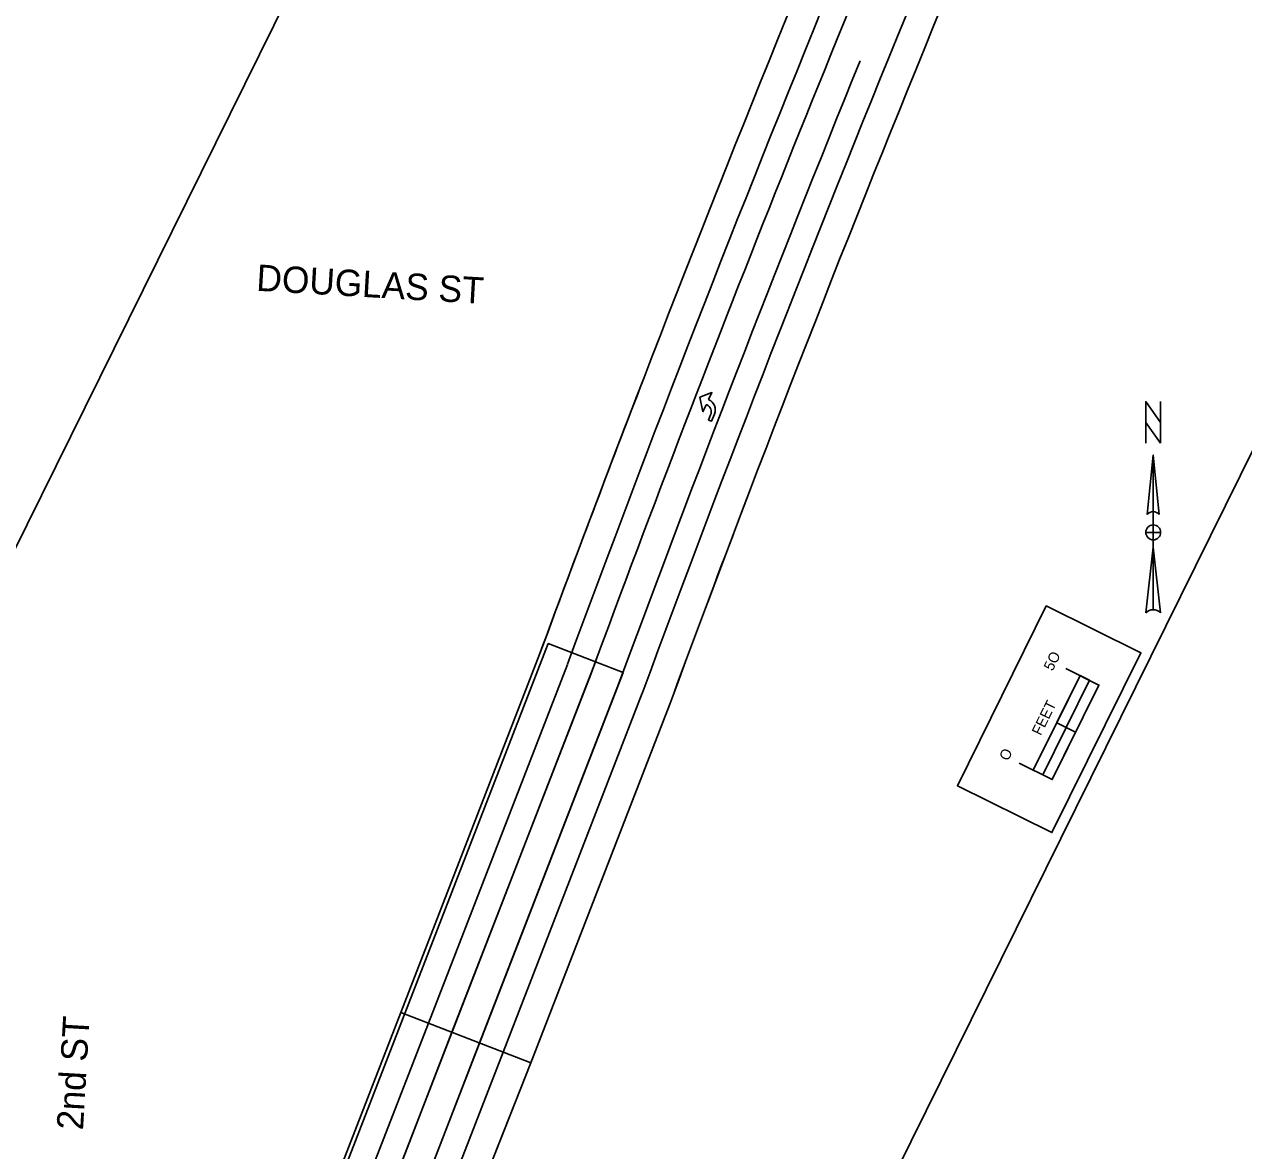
# Model space of a CAD drawing. Extents: x 14104283 to 14120882, y 8635219 to 8671666.
# Drawn here: x 14119794 to 14120371, y 8670437 to 8670971 of the extents above; entities that cross this region are included whole.
import ezdxf

# ---------------------------------------------------------------- set-up
doc = ezdxf.new("R2010")
doc.units = 0
for name, color, linetype in [('Cell', 7, 'Continuous'), ('Default', 7, 'Continuous'), ('dsnCellsNorthArrow', 7, 'Continuous'), ('dsnCellsScaleBlock', 7, 'Continuous'), ('dsnNonPlotable', 7, 'Continuous'), ('dsnPaintExistingBrokenLaneLineWhite', 7, 'Continuous'), ('dsnPaintExistingEdgeLineRightWhite', 7, 'Continuous'), ('dsnPaintExistingNoPassingYellow', 7, 'Continuous'), ('dsnPaintExistingSymbolWhite', 7, 'Continuous'), ('dsnShadingPaved', 7, 'Continuous'), ('dsnTextOverlapEven', 7, 'Continuous'), ('dsnTextOverlapOdd', 7, 'Continuous')]:
    doc.layers.add(name, color=color, linetype=linetype)

msp = doc.modelspace()

# ---------------------------------------------------------------- linework, layer by layer
at = {"layer": 'Cell'}
for p, q in [((14120117.15, 8670790.72), (14120116.85, 8670790.83)), ((14120117.97, 8670793.22), (14120118.14, 8670793.15))]:
    msp.add_line(p, q, dxfattribs=at)
for points in [[(14120113.8, 8670794.36), (14120119.54, 8670796.55), (14120117.97, 8670793.22)], [(14120113.8, 8670794.36), (14120119.54, 8670796.55), (14120117.97, 8670793.22)], [(14120116.85, 8670790.83), (14120115.29, 8670787.5), (14120113.8, 8670794.36)], [(14120116.85, 8670790.83), (14120115.29, 8670787.5), (14120113.8, 8670794.36)], [(14120117.15, 8670790.72), (14120116.85, 8670790.83)], [(14120117.97, 8670793.22), (14120118.14, 8670793.15)], [(14120120.76, 8670786.39), (14120119.36, 8670782.99), (14120117.98, 8670783.56), (14120118.97, 8670785.99)], [(14120120.76, 8670786.39), (14120119.36, 8670782.99), (14120117.98, 8670783.56), (14120118.97, 8670785.99)]]:
    msp.add_lwpolyline(points, dxfattribs=at)
for centre, major_axis in [((14120115.75, 8670787.31), (-1.4, -3.4)), ((14120115.75, 8670787.31), (-1.4, -3.4)), ((14120116.15, 8670788.28), (-2, -4.86)), ((14120116.15, 8670788.28), (-2, -4.86))]:
    msp.add_ellipse(centre, major_axis=major_axis, ratio=0.9474, start_param=1.570796, end_param=3.141593, dxfattribs=at)
at = {"layer": 'Default'}
for p, q in [((14119972.19, 8670502.91), (14120038.08, 8670672.89)), ((14120099.62, 8670649.04), (14120033.72, 8670479.06)), ((14120033.72, 8670479.06), (14119972.19, 8670502.91))]:
    msp.add_line(p, q, dxfattribs=at)
msp.add_lwpolyline([(14119861.3, 8670216.88), (14119920.98, 8670193.76), (14120033.72, 8670479.06), (14119972.19, 8670502.91)], close=True, dxfattribs=at)
for centre in [(14129121.85, 8667322.17), (14129183.39, 8667298.31)]:
    msp.add_arc(centre, 9682.06, 155.679047, 159.752527, dxfattribs=at)
at = {"layer": 'dsnCellsNorthArrow'}
for p, q in [((14120328.64, 8670766.96), (14120331.45, 8670738.79)), ((14120328.64, 8670766.96), (14120328.64, 8670693.71)), ((14120325.82, 8670738.79), (14120325.82, 8670738.79)), ((14120325.93, 8670739.05), (14120326.45, 8670739.63)), ((14120328.64, 8670726.82), (14120328.64, 8670726.81)), ((14120325.12, 8670692.3), (14120328.64, 8670723.29))]:
    msp.add_line(p, q, dxfattribs=at)
msp.add_lwpolyline([(14120332.16, 8670772.59), (14120325.12, 8670782.45), (14120325.12, 8670792.31), (14120332.16, 8670782.45)], close=True, dxfattribs=at)
for points in [[(14120325.12, 8670772.59), (14120325.12, 8670792.31), (14120332.16, 8670782.45), (14120332.16, 8670792.31)], [(14120325.82, 8670738.79), (14120328.64, 8670766.96), (14120328.64, 8670740.2)], [(14120332.16, 8670730.34), (14120328.64, 8670730.34), (14120328.64, 8670733.86)], [(14120328.64, 8670726.81), (14120328.64, 8670730.34), (14120325.12, 8670730.34)], [(14120328.64, 8670693.71), (14120328.64, 8670723.29), (14120332.16, 8670692.31)]]:
    msp.add_lwpolyline(points, dxfattribs=at)
for centre, radius, start, end in [((14120328.64, 8670736.67), 3.52, 90.02039, 143.12574), ((14120328.64, 8670736.68), 3.52, 36.84806, 90.02184), ((14120328.64, 8670730.34), 3.52, 90, 180), ((14120328.64, 8670730.34), 3.52, 0, 90), ((14120328.64, 8670730.34), 3.52, 180, 270), ((14120328.64, 8670730.34), 3.52, 270, 360), ((14120328.64, 8670688.61), 5.1, 89.98939, 133.61895), ((14120328.64, 8670688.61), 5.11, 46.40206, 90.00064)]:
    msp.add_arc(centre, radius, start, end, dxfattribs=at)
at = {"layer": 'dsnCellsScaleBlock'}
msp.add_line((14120291.87, 8670635.63), (14120282.9, 8670640.06), dxfattribs=at)
msp.add_line((14120291.87, 8670635.63), (14120282.9, 8670640.06), dxfattribs=at)
for points in [[(14120235.85, 8670610.33), (14120277.96, 8670695.49), (14120322.78, 8670673.33), (14120280.67, 8670588.17)], [(14120280.67, 8670588.17), (14120235.85, 8670610.33), (14120277.96, 8670695.49), (14120322.78, 8670673.33)], [(14120287.35, 8670637.86), (14120298.43, 8670660.27), (14120293.98, 8670662.47), (14120282.9, 8670640.06)], [(14120280.78, 8670613.22), (14120291.87, 8670635.63), (14120287.35, 8670637.86), (14120276.27, 8670615.45)]]:
    msp.add_lwpolyline(points, close=True, dxfattribs=at)
for points in [[(14120265.1, 8670620.97), (14120280.78, 8670613.22), (14120302.95, 8670658.04), (14120287.26, 8670665.79)], [(14120271.82, 8670617.65), (14120293.98, 8670662.47)]]:
    msp.add_lwpolyline(points, dxfattribs=at)
at = {"layer": 'dsnNonPlotable'}
msp.add_lwpolyline([(14119506.15, 8670149.79), (14120200.88, 8671554.92), (14120653.57, 8671331.1), (14119958.84, 8669925.97)], close=True, dxfattribs=at)
at = {"layer": 'dsnPaintExistingBrokenLaneLineWhite'}
for p, q in [((14119985.24, 8670497.85), (14120051.13, 8670667.83)), ((14120020.67, 8670484.12), (14120086.56, 8670654.1)), ((14119874.41, 8670211.95), (14119985.24, 8670497.85)), ((14119909.84, 8670198.21), (14120020.67, 8670484.12))]:
    msp.add_line(p, q, dxfattribs=at)
for centre in [(14129134.9, 8667317.11), (14129170.33, 8667303.37)]:
    msp.add_arc(centre, 9682.06, 155.679047, 159.752527, dxfattribs=at)
at = {"layer": 'dsnPaintExistingEdgeLineRightWhite'}
for p, q in [((14120038.08, 8670672.89), (14119972.19, 8670502.91)), ((14120033.72, 8670479.06), (14120099.62, 8670649.04)), ((14119972.19, 8670502.91), (14119897.54, 8670310.36)), ((14119920.98, 8670193.76), (14120033.72, 8670479.06))]:
    msp.add_line(p, q, dxfattribs=at)
for centre, start in [((14129121.85, 8667322.17), 158.955067), ((14129183.39, 8667298.31), 159.24373)]:
    msp.add_arc(centre, 9682.06, start, 159.752527, dxfattribs=at)
at = {"layer": 'dsnPaintExistingNoPassingYellow'}
for p, q in [((14120062.32, 8670663.5), (14119996.43, 8670493.52)), ((14120009.48, 8670488.46), (14120075.37, 8670658.44)), ((14119996.43, 8670493.52), (14119885.6, 8670207.61)), ((14119898.65, 8670202.55), (14120009.48, 8670488.46))]:
    msp.add_line(p, q, dxfattribs=at)
for centre, start in [((14129146.09, 8667312.77), 156.77428), ((14129159.14, 8667307.71), 157.878476)]:
    msp.add_arc(centre, 9682.06, start, 159.752527, dxfattribs=at)
at = {"layer": 'dsnPaintExistingSymbolWhite'}
for p, q in [((14120117.15, 8670790.72), (14120116.85, 8670790.83)), ((14120117.97, 8670793.22), (14120118.14, 8670793.15))]:
    msp.add_line(p, q, dxfattribs=at)
for points in [[(14120113.8, 8670794.36), (14120119.54, 8670796.55), (14120117.97, 8670793.22)], [(14120113.8, 8670794.36), (14120119.54, 8670796.55), (14120117.97, 8670793.22)], [(14120116.85, 8670790.83), (14120115.29, 8670787.5), (14120113.8, 8670794.36)], [(14120116.85, 8670790.83), (14120115.29, 8670787.5), (14120113.8, 8670794.36)], [(14120117.15, 8670790.72), (14120116.85, 8670790.83)], [(14120117.97, 8670793.22), (14120118.14, 8670793.15)], [(14120120.76, 8670786.39), (14120119.36, 8670782.99), (14120117.98, 8670783.56), (14120118.97, 8670785.99)], [(14120120.76, 8670786.39), (14120119.36, 8670782.99), (14120117.98, 8670783.56), (14120118.97, 8670785.99)]]:
    msp.add_lwpolyline(points, dxfattribs=at)
for centre, major_axis in [((14120115.75, 8670787.31), (-1.4, -3.4)), ((14120115.75, 8670787.31), (-1.4, -3.4)), ((14120116.15, 8670788.28), (-2, -4.86)), ((14120116.15, 8670788.28), (-2, -4.86))]:
    msp.add_ellipse(centre, major_axis=major_axis, ratio=0.9474, start_param=1.570796, end_param=3.141593, dxfattribs=at)
at = {"layer": 'dsnShadingPaved'}
for points in [[(14119863.22, 8670216.29), (14120042.07, 8670677.65), (14120064.44, 8670668.98), (14119885.6, 8670207.61)], [(14119885.6, 8670207.61), (14120064.44, 8670668.98), (14120077.5, 8670663.92), (14119922.69, 8670264.56), (14119945.07, 8670255.89), (14119945.07, 8670255.89), (14119921.03, 8670193.88)]]:
    msp.add_lwpolyline(points, dxfattribs=at)

# ---------------------------------------------------------------- texts
at = {"layer": 'dsnCellsScaleBlock'}
for s, p in [('5O', (14120280.97, 8670664.36)), ('FEET', (14120275.34, 8670633.79)), ('O', (14120259.89, 8670621.73))]:
    msp.add_text(s, height=5, rotation=63.69117, dxfattribs=at).set_placement(p)
at = {"layer": 'dsnTextOverlapEven'}
msp.add_text('2nd ST', height=12.5, rotation=86.69117, dxfattribs=at).set_placement((14119821.61, 8670446.97))
at = {"layer": 'dsnTextOverlapOdd'}
msp.add_text('DOUGLAS ST', height=12.5, rotation=356.69117, dxfattribs=at).set_placement((14119903.52, 8670844.82))

doc.saveas('drawing.dxf')
